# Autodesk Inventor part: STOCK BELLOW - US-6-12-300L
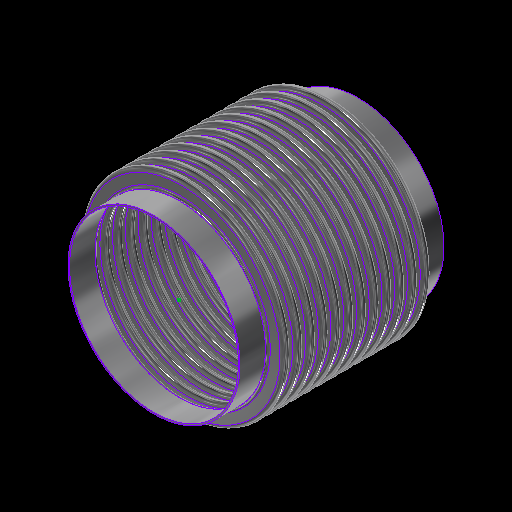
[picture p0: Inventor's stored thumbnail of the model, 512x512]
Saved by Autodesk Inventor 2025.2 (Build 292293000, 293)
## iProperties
Category: 22 GA (0.030 THICK)
RuleStatus: InUse
Created: 2024-01
Part Number: STOCK BELLOW - US-6-12-300L
Project: =STOCK BELLOWS: <Stock Number><SFILL>
Material: ASTM A240-304
Description: =STOCK BELLOWS: <Stock Number>, <SID_> I.D., <SOD_> O.D., <SPLY_> PLY, <Category>, <SNET_CONS> CONS.<PITCH_><STANGENT_> TANGENT<SFILL>
Document SubType Name: Sheet Metal
Designer: GS
Stock Number: U.S-6-12-300L
Surface Area: 6070.08 cm^2
Volume: 458.823 cm^3
Sheet Metal Rule: Default
Appearance: STAINLESS STEEL
Mass: 3696.87 g
Density: 8.05729 g/cm^3
THK: 0.036
ID: 3.500
OD: 4.250
CONS_: 2
PITCH: 0.500
TANGENT: 0.500
BELLOWS_UPSET: 0.000
d79: 1.000
d82: 1.000
d83: 26.000
d84: 24.000
d174: 8
d214: 8
STHK_: 0.030
SID_: 6.625
SOD_: 8.000
SPITCH_: 0.500
STANGENT__: 1.000
SBELLOWS_UPSET_: 0.000
SDIFF_TAN: 1.000
d252: 2
d275: 2
d287: 0.050
d289: 0.500
d290: 0.000
SOD_NECK: 6 3/4
PLY: 1
PSET: 4.178
PBAR: 1.035
COUNTER: 1.500
NET_TUBE: 3.071
CONS: 2
S_CONS: 0
NET_CONS: 2
ID_M: 88.90 mm
OD_M: 107.95 mm
THK_M: 0.91 mm
ID_U: 3.500 in
OD_U: 4.250 in
THK_U: 0.036 in
TANGENT2: 0.500
TAN_TO_TAN: 1.000 in
d80: 2.571
d81: 10
SID: 2.375
SCONS_: 12
SPITCH: 0.250
STANGENT_: 1.000
SBELLOWS_UPSET: 0.000
SNET_CONS: 12
SS_CONS: 0
SCONS: 8
d190: 8
d191: 1
d192: 1
d193: 8
d194: 0
SIZE: 6.00
PRESSURE: 300
d230: 8
STANGENT: 4.000
SPLY_: 2
d233: 8
d234: 0
d263: 2
d265: 1
d268: 2
d269: 0
d286: 2
d288: 1
d291: 2
d292: 0
SREROLL: 0.750
BLETP: 1.000 ul
PRES_Copy: 85
MATTABLE: 20 GA (0.036 THICK)
PART_NUMBER: U.S-6-12-300L
PITCH_: =, <SPITCH_> PITCH,
CFILL: .
SFILL: .
MESH: ,
COMP: 1.26
EXT: 0.63
LAT: 0.34
ANG: 573
ASR: 1872
LSR: 4172
ANSR: 218
PRES: 300
COMPM: 12.6
EXTM: 6.3
LATM: 3.40
ASRM: 327.843
PRESM: 20.684
LSRM: 730.642
ANSRM: 38.178
TEMPMIN: 20
TEMPMAX: 800
TEMPMINM: -7
TEMPMAXM: 427
WEIGHTM: 3.697
WEIGHT: 8.150
Author: GS
Keywords: 20 GA (0.036 THICK)
Comments: =STOCK BELLOW - <STOCK NUMBER>
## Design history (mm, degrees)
sketch "Sketch2"
  geometry: L1 (0, -177.245)-(0, 562.856) reference; L2 (45.364, 0)-(44.45, 0); L3 (48.082, -2.718)-(50.343, -2.718); L4 (48.082, -3.632)-(50.343, -3.632); L5 (50.343, -9.982)-(48.082, -9.982); L6 (50.343, -9.068)-(48.082, -9.068); L7 (45.364, -12.7)-(44.45, -12.7); L8 (48.082, 0)-(48.082, -12.7); L9 (50.343, -6.35)-(53.975, -6.35); L10 (44.45, 0)-(44.45, -12.7); L11 (20.376, 102.841)-(20.376, 101.926); L12 (58.262, 457.127)-(58.262, 349.177); L13 (58.262, 444.427)-(58.262, 336.477); L14 (93.133, -58.817)-(93.133, -71.517); L15 (118.746, -66.401)-(118.746, -66.401); L16 (50.343, -9.068)-(50.343, -9.982); L17 (48.082, -9.068)-(48.082, -9.982); L18 (48.082, -9.525)-(50.343, -9.525); L19 (53.975, 0)-(53.975, -12.7); L20 (-50.343, -9.068)-(-50.343, -9.982); L21 (-50.343, -2.718)-(-48.082, -2.718); L22 (-50.343, -3.632)-(-48.082, -3.632); L23 (-48.082, -9.068)-(-50.343, -9.068); L24 (-50.343, -9.525)-(-48.082, -9.525); L25 (-48.082, -9.982)-(-50.343, -9.982); L26 (-48.082, -9.068)-(-48.082, -9.982); L27 (-44.45, 0.653)-(-44.45, -12.047); L28 (-48.082, -6.35)-(-44.45, -6.35); L29 (-50.343, 0.653)-(-50.343, -12.7); L30 (-53.061, 0)-(-53.975, 0); L31 (-53.975, 0)-(-53.975, -12.7); L32 (-53.061, -12.7)-(-53.975, -12.7); A1 r 2.718 centre (48.082, 0) between (45.364, 0) and (48.082, -2.718); A2 r 3.632 centre (48.082, 0) between (44.45, 0) and (48.082, -3.632); A3 r 3.632 centre (50.343, -6.35) between (50.343, -9.982) and (50.343, -2.718); A4 r 2.718 centre (50.343, -6.35) between (50.343, -9.068) and (50.343, -3.632); A5 r 2.718 centre (48.082, -12.7) between (48.082, -9.982) and (45.364, -12.7); A6 r 3.632 centre (48.082, -12.7) between (48.082, -9.068) and (44.45, -12.7); A7 r 3.175 centre (50.343, -6.35) between (50.343, -9.525) and (53.518, -6.35); A8 r 3.175 centre (48.082, -12.7) between (48.082, -9.525) and (44.907, -12.7); A9 r 2.718 centre (-50.343, -12.7) between (-50.343, -9.982) and (-53.061, -12.7); A10 r 2.718 centre (-48.082, -6.35) between (-48.082, -9.068) and (-48.082, -3.632); A11 r 3.175 centre (-48.082, -6.35) between (-48.082, -9.525) and (-44.907, -6.35); A12 r 3.632 centre (-48.082, -6.35) between (-48.082, -9.982) and (-48.082, -2.718); A13 r 3.175 centre (-50.343, -12.7) between (-50.343, -9.525) and (-53.518, -12.7); A14 r 3.632 centre (-50.343, -12.7) between (-50.343, -9.068) and (-53.975, -12.7); A15 r 2.718 centre (-50.343, 0) between (-53.061, 0) and (-50.343, -2.718); A16 r 3.632 centre (-50.343, 0) between (-53.975, 0) and (-50.343, -3.632); 10 further points
  constraints: 62 end point, 38 point on circle, 20 tangent, 16 centre point, 12 parallel, 9 midpoint, 7 vertical, 6 coincident, 6 concentric, 6 point on line, 4 equal radius, 4 perpendicular, 3 horizontal, 1 collinear, 1 horizontal alignment, 10 other
  dimensions: "THK" = 0.9144 distance of L11.start L11.end; "ID" = 88.9 distance of L11.end point (20.376, 13.026); "OD" = 107.95 distance of L12.start L12.end; "PITCH" = 12.7 distance of L12.start L13.start; "TANGENT" = 12.7 distance of L14.start L14.end; "BELLOWS_UPSET" = 0 distance of L15.start L15.end; "d43" = 88.9 diameter of L10 L1 (= ID); "d44" = 107.95 diameter of L9.end L1 (= OD); "d45" = 0.9144 distance between parallel lines of L5 L6 (computed from THK, PLY); "d46" = 3.6322 radius of A3 (computed from PITCH, THK, PLY); "UPSET_PITCH" = 12.7 distance of L2.end L7.end (derived); "SIDEWALL_ANGLE" = 360 deg dimension on L3 L9 (derived); "CON_GAP" = 5.4356 distance of point (48.082, -9.068) point (48.082, -3.632) (derived); "TAN1" = 4.98728 dimension on A8 (derived); "TAN2" = 4.98728 dimension on A7 (derived); "LEG1" = 2.2606 distance of L18.start L18.end (derived); "d278" = 0.9144 distance between parallel lines of L25 L23 (derived); "d279" = 3.6322 radius of A12 (derived); "d280" = 12.7 distance of L30.end L31.end (derived); "d281" = 360 deg dimension on L21 L28 (derived); "d282" = 5.4356 distance of point (-50.343, -9.068) point (-50.343, -3.632) (derived); "d283" = 4.98728 dimension on A13 (derived); "d284" = 4.98728 dimension on A11 (derived); "d285" = 2.2606 distance of L24.start L24.end (derived); "d293" = 88.9 diameter of L27 L1 (derived); "d294" = 107.95 diameter of L31 L1 (derived)
  node "Sketch Rectangular Pattern1" dims "d31" = 25.4, "ID" = 88.9
  node "Sketch Rectangular Pattern2" dims "d39" = 25.4, "PITCH" = 12.7
revolve "CONS" stored, may be unused: angle "d48" = 90 deg
node "BELLOW MIDPLANE"
pattern_linear "Rectangular Pattern2" dims "d52" = 12.7 (= UPSET_PITCH)
sketch "Sketch5"
  geometry: C1 r 45.364 at (0, 0) reference; C2 r 44.45 at (0, 0) reference
extrude "TANGENT" new body sketch "Sketch5" distance "d53" = 12.7 (= TANGENT); taper "d54" = 0 deg
revolve "SAMETAN" stored, may be unused: angle "d65" = 90 deg
revolve "DIFFTAN" stored, may be unused: angle "d70" = 90 deg
sketch "Sketch9"
  geometry: L1 (53.319, 0)-(-53.319, 0) reference; L2 (0, -17.78)-(0, 17.78) reference; L3 (38.085, 0)-(-38.085, 0); L4 (38.085, -11.906)-(38.085, 11.906); L5 (25.385, -11.906)-(25.385, 11.906); L6 (13.15, 11.906)-(13.15, -11.906); L7 (-25.385, -11.906)-(-25.385, 11.906); L8 (-38.085, -11.906)-(-38.085, 11.906); L9 (37.291, -11.906)-(37.291, 11.906); L10 (38.085, -11.906)-(37.291, -11.906); L11 (38.085, 11.906)-(37.291, 11.906); L12 (13.546, 11.906)-(12.753, 11.906); L13 (12.753, 11.906)-(12.753, -11.906); L14 (12.753, -11.906)-(13.546, -11.906); L15 (13.546, -11.906)-(13.546, 11.906); L16 (-13.546, 11.906)-(-13.546, -11.906); L17 (-13.15, 11.906)-(-13.15, -11.906); L18 (-13.546, -11.906)-(-12.753, -11.906); L19 (-12.753, -11.906)-(-12.753, 11.906); L20 (-12.753, 11.906)-(-13.546, 11.906); L21 (-38.085, -11.906)-(-37.291, -11.906); L22 (-37.291, -11.906)-(-37.291, 11.906); L23 (-37.291, 11.906)-(-38.085, 11.906); L24 (-38.085, 11.906)-(-38.085, -11.906); L25 (38.085, -0.397)-(-38.085, -0.397); L26 (-38.085, -0.397)-(-38.085, 0.397); L27 (-38.085, 0.397)-(38.085, 0.397); L28 (38.085, 0.397)-(38.085, -0.397); L29 (-38.085, 11.906)-(38.085, 11.906); L30 (38.085, 11.906)-(38.085, 12.7); L31 (38.085, 12.7)-(-38.085, 12.7); L32 (-38.085, 12.7)-(-38.085, 11.906); L33 (38.085, -11.906)-(-38.085, -11.906); L34 (-38.085, -11.906)-(-38.085, -12.7); L35 (-38.085, -12.7)-(38.085, -12.7); L36 (38.085, -12.7)-(38.085, -11.906); 30 further points
  constraints: 68 end point, 13 midpoint, 13 parallel, 8 horizontal, 7 perpendicular, 6 equal length, 3 point on line, 2 vertical, 14 other
  dimensions: "d115" = 23.8125 distance of L4.start L4.end (derived); "d116" = 12.7 distance between parallel lines of L4 L5 (derived); "d117" = 12.23516 distance between parallel lines of L5 L6 (derived); "d125" = 38.53427 distance between parallel lines of L7 L6 (derived); "d127" = 12.7 distance between parallel lines of L8 L7 (derived); "d128" = 24.93516 distance between parallel lines of L6 L4 (derived); "d130" = 76.16943 distance between parallel lines of L8 L4 (derived); "RULER_THK" = 0.79375 distance between parallel lines of L4 L9; "d135" = 0.79375 distance of L13.end L14.end (derived); "d138" = 26.29911 distance of L13.end L16.end (derived); "d143" = 0.79375 distance of L22.end L8.end (derived); "d144" = 0.79375 distance between parallel lines of L27 L25 (derived)
extrude "RULER" join sketch "Sketch9" distance "d149" = 0.79375 (derived); taper "d150" = 0 deg
extrude "BARS" join sketch "Sketch9" distance "d151" = 0.79375 (derived); taper "d152" = 0 deg
pattern_linear "Rectangular Pattern4" dims "d155" = 26.29911 (derived)
sketch "Sketch13"
  geometry: L1 (93.149, -52.467)-(93.149, -77.867); L2 (85.662, 0)-(84.138, 0); L3 (85.662, -12.7)-(84.138, -12.7); L4 (97.663, -10.287)-(88.075, -10.287); L5 (97.663, -8.763)-(88.075, -8.763); L6 (97.663, -6.35)-(101.6, -6.35); L7 (88.075, -2.413)-(97.663, -2.413); L8 (88.075, 0)-(88.075, -12.7); L9 (84.138, 0)-(84.138, -12.7); L10 (58.254, -293.231)-(58.254, -496.431); L11 (58.254, -305.931)-(58.254, -509.131); L12 (58.254, -331.331)-(58.254, -534.531); L13 (58.254, -344.031)-(58.254, -547.231); L14 (58.254, -356.731)-(58.254, -559.931); L15 (58.254, -369.431)-(58.254, -572.631); L16 (58.254, -382.131)-(58.254, -585.331); L17 (58.254, -318.631)-(58.254, -521.831); L18 (20.376, 102.688)-(20.376, 101.926); L19 (88.075, -3.937)-(97.663, -3.937); L20 (0, -722.935)-(0, 240.292) reference; L21 (-23.752, 0)-(142.514, 0) reference; A1 r 2.413 centre (88.075, 0) between (85.662, 0) and (88.075, -2.413); A2 r 2.413 centre (88.075, -12.7) between (88.075, -10.287) and (85.662, -12.7); A3 r 3.937 centre (88.075, -12.7) between (88.075, -8.763) and (84.138, -12.7); A4 r 2.413 centre (97.663, -6.35) between (97.663, -8.763) and (97.663, -3.937); A5 r 3.937 centre (97.663, -6.35) between (97.663, -10.287) and (97.663, -2.413); A6 r 3.937 centre (88.075, 0) between (84.138, 0) and (88.075, -3.937); 6 further points; 1 other entity
  constraints: 38 end point, 15 point on circle, 9 tangent, 6 centre point, 6 parallel, 5 vertical alignment, 4 point on line, 4 vertical, 3 coincident, 3 concentric, 2 collinear, 2 equal radius, 1 horizontal, 1 perpendicular, 23 other
  dimensions: "SBELLOWS_UPSET_" = 0 distance of point (118.762, -66.401) point (118.762, -66.401); "STOTAL_THK_BELLOW__" = 1.524 distance between parallel lines of L4 L5 (derived); "d224" = 3.937 radius of A5 (derived); "d225" = 12.7 distance of L2.end L3.end (derived); "SSIDEWALL_ANGLE_" = 0 deg angle of L7 L6 (derived); "SSCON_GAP_" = 4.826 distance of point (88.075, -8.763) point (88.075, -3.937) (derived); "d235" = 168.275 diameter of L9 L20 (derived); "d236" = 203.2 diameter of L6.end L20 (derived)
  node "Sketch Rectangular Pattern4" dims "d228" = 25.4
  node "Sketch Rectangular Pattern5" dims "d229" = 25.4
revolve "SBELLOW" stored, may be unused: angle "d197" = 90 deg
pattern_linear "Rectangular Pattern5" dims "d204" = 12.7 (derived)
revolve "STANGENT" stored, may be unused: angle "d240" = 90 deg
revolve "SSAMETAN" stored, may be unused: angle "d241" = 90 deg
revolve "SDIFFTAN" stored, may be unused: angle "d246" = 90 deg
revolve "INVCON" stored, may be unused: angle "d295" = 90 deg
pattern_linear "Rectangular Pattern6" dims "d298" = 12.7 (derived)
revolve "INVTANGENT" stored, may be unused: angle "d302" = 90 deg
revolve "INVSAMETAN" stored, may be unused: angle "d307" = 90 deg
revolve "INVDIFFTAN" stored, may be unused: angle "d312" = 90 deg
sketch "ID BELLOW MOUNT CALC"
  geometry: L1 (44.45, 0)-(38.1, 0); L2 (38.1, 0)-(38.1, 12.7); L3 (38.1, 12.7)-(44.45, 12.7); L4 (44.45, 12.7)-(44.45, 0); L5 (36.513, 12.7)-(35.598, 12.7); L6 (35.598, 12.7)-(35.598, 0); L7 (35.598, 0)-(36.513, 0); L8 (36.513, 0)-(36.513, 12.7); L9 (0, -2.54)-(0, 15.24) reference; L10 (-8.89, 0)-(53.34, 0) reference; 1 further point
  constraints: 16 end point, 5 parallel, 2 collinear, 2 horizontal, 2 perpendicular
  dimensions: "d314" = 12.7 distance of L5.end L6.end (derived); "d315" = 0.9144 distance of L5.start L5.end (derived); "IG" = 1.5875 distance between parallel lines of L2 L8; "PIPE_OD" = 88.9 diameter of L4 L9; "PIPE_WALL" = 6.35 distance of L2.end L3.end; "ID_MT_BELLOW" = 71.1962 diameter of L6 L9 (derived)
revolve "CFILL" stored, may be unused: angle "d320" = 90 deg
pattern_linear "Rectangular Pattern7" dims "d323" = 12.7 (derived)
revolve "SFILL" stored, may be unused: angle "d324" = 90 deg
pattern_linear "Rectangular Pattern8" dims "d327" = 12.7 (derived)
node "STOCK BELLOW MIDPLANE"
node "BELLOW"
sketch "Sketch6"
  geometry: L1 (-12.7, 45.364)-(0, 45.364); L2 (0, 45.364)-(0, 44.45); L3 (0, 44.45)-(-12.7, 44.45); L4 (-12.7, 44.45)-(-12.7, 45.364); L5 (10.16, 0)-(-60.96, 0) reference; L6 (-38.1, -89.422)-(-38.1, 153.44) reference; 1 further point
  constraints: 8 end point, 2 parallel, 1 horizontal, 1 perpendicular
  dimensions: "d61" = 12.7 distance of L2.end L3.end (derived); "d62" = 0.9144 distance of L1.end L2.end (derived); "d63" = 88.9 diameter of L3 L5 (derived); "d64" = 25.4 distance between parallel lines of L4 L6 (derived)
sketch "Sketch12"
  geometry: 1 further point
sketch "Sketch14"
  geometry: L1 (-25.4, 85.662)-(0, 85.662); L2 (0, 85.662)-(0, 84.138); L3 (0, 84.138)-(-25.4, 84.138); L4 (-25.4, 84.138)-(-25.4, 85.662); L5 (5.08, 0)-(-30.48, 0) reference; L6 (0, -17.132)-(0, 102.794) reference; 1 further point
  constraints: 8 end point, 2 parallel, 1 collinear, 1 horizontal, 1 perpendicular
  dimensions: "d237" = 1.524 distance of L3.end L1.start (derived); "d238" = 168.275 diameter of L3 L5 (derived); "d239" = 25.4 distance of L1.start L1.end (derived); "SOD_NECK" = 171.323 diameter of L1 L5 (derived)
sketch "Sketch15"
  geometry: L1 (-17.132, 0)-(102.794, 0) reference; L2 (84.138, -152.4)-(85.662, -152.4); L3 (85.662, -152.4)-(85.662, -177.8); L4 (85.662, -177.8)-(84.138, -177.8); L5 (84.138, -177.8)-(84.138, -152.4); L6 (0, -215.9)-(0, 50.8) reference; 1 further point
  constraints: 8 end point, 2 parallel, 1 horizontal, 1 perpendicular
  dimensions: "d205" = 25.4 distance of L4.end L2.start (derived); "d206" = 1.524 distance of L3.end L4.end (derived); "d207" = 168.275 diameter of L5 L6 (derived); "d208" = 152.4 distance between parallel lines of L1 L2 (derived)
node "TANGENT_"
node "SAME_TAN"
sketch "Sketch8"
  geometry: L1 (45.364, -25.4)-(44.45, -25.4); L2 (44.45, -25.4)-(44.45, -38.1); L3 (44.45, -38.1)-(45.364, -38.1); L4 (45.364, -38.1)-(45.364, -25.4); L5 (0, -48.26)-(0, 22.86) reference; L6 (-89.422, 0)-(153.44, 0) reference; 1 further point
  constraints: 8 end point, 2 parallel, 1 horizontal, 1 perpendicular
  dimensions: "d66" = 88.9 diameter of L2 L5 (derived); "TOTAL_THK_BELLOW" = 0.9144 distance of L2.end L3.end (derived); "d68" = 25.4 distance between parallel lines of L1 L6 (derived); "d69" = 12.7 distance of L1.end L2.end (derived)
node "DIFF_TAN"
node "Sketch Rectangular Pattern3" dims "d138" = 26.29911 (derived), "d141" = 25.4
node "SBELLOW_"
node "STANGENT_"
node "SSAME_TAN"
sketch "Sketch16"
  geometry: L1 (85.661, -152.4)-(84.138, -152.4); L2 (84.138, -152.4)-(84.138, -177.8); L3 (84.138, -177.8)-(85.662, -177.8); L4 (85.662, -177.8)-(85.661, -152.4); L5 (0, -215.9)-(0, 50.8) reference; L6 (-17.132, 0)-(102.794, 0) reference; 1 further point
  constraints: 8 end point, 2 parallel, 1 horizontal, 1 perpendicular
  dimensions: "SDIFF_TAN" = 25.4 distance of L3.end L1.start; "d243" = 1.524 distance of L2.end L3.end (derived); "d244" = 152.4 distance between parallel lines of L1 L6 (derived); "d245" = 168.275 diameter of L2 L5 (derived)
node "SDIFF_TAN"
body "Solid15"
sketch "Sketch17"
  geometry: L1 (53.975, 12.7)-(53.061, 12.7); L2 (53.061, 12.7)-(53.061, 0); L3 (53.061, 0)-(53.975, 0); L4 (53.975, 0)-(53.975, 12.7); L5 (0, -2.54)-(0, 15.24) reference; L6 (-10.795, 0)-(64.77, 0) reference; 2 further points
  constraints: 8 end point, 2 parallel, 1 horizontal, 1 midpoint, 1 perpendicular, 1 point on line
  dimensions: "INVTANGENT" = 12.7 distance of L3.end L1.start (derived); "d300" = 0.9144 distance of L1.start L1.end (derived); "d301" = 107.95 diameter of L4 L5 (derived)
body "Solid16"
sketch "Sketch18"
  geometry: L1 (53.975, -25.4)-(53.061, -25.4); L2 (53.061, -25.4)-(53.061, -38.1); L3 (53.061, -38.1)-(53.975, -38.1); L4 (53.975, -38.1)-(53.975, -25.4); L5 (-10.795, 0)-(64.77, 0) reference; L6 (0, -48.26)-(0, 22.86) reference; 1 further point
  constraints: 8 end point, 2 parallel, 1 horizontal, 1 perpendicular
  dimensions: "d303" = 25.4 distance between parallel lines of L1 L5 (derived); "d304" = 12.7 distance of L3.end L1.start (derived); "d305" = 0.9144 distance of L2.end L3.end (derived); "d306" = 107.95 diameter of L4 L6 (derived)
body "Solid17"
sketch "Sketch19"
  geometry: L1 (53.975, -25.4)-(53.061, -25.4); L2 (53.061, -25.4)-(53.061, -38.1); L3 (53.061, -38.1)-(53.975, -38.1); L4 (53.975, -38.1)-(53.975, -25.4); L5 (0, -48.26)-(0, 22.86) reference; L6 (-10.795, 0)-(64.77, 0) reference; 1 further point
  constraints: 8 end point, 2 parallel, 1 horizontal, 1 perpendicular
  dimensions: "d308" = 12.7 distance of L1.end L2.end (derived); "d309" = 107.95 diameter of L4 L5 (derived); "d310" = 0.9144 distance of L2.end L3.end (derived); "d311" = 25.4 distance between parallel lines of L1 L6 (derived)
body "Solid18"
body "Solid19"
body "Solid20"
other parameters: "BMPL" = -76.2, "PSET" = 106.1212 (computed from OD, THK, PLY) [user parameter], "PBAR" = 26.29911 (= 0.570796 x PITCH + OD - ID) [user parameter; used in 1 equation term], "COUNTER" = 15 [user parameter], "NET_TUBE" = 77.99823 (computed from CONS_, PBAR, TANGENT) [user parameter], "S_CONS" = 0 [user parameter; used in 1 equation term], "ID_M" = 88.9 (= ID) [user parameter], "OD_M" = 107.95 (= OD) [user parameter], "THK_M" = 0.9144 (= THK) [user parameter], "ID_U" = 88.9 (= ID) [user parameter], "OD_U" = 107.95 (= OD) [user parameter], "THK_U" = 0.9144 (= THK) [user parameter], "D_UNITS" = 0 [user parameter], "TANGENT2" = 12.7 [user parameter], "TAN_TO_TAN" = 25.4 [user parameter], "OD_NECK" = 90.7288 [user parameter], "d79" = 25.4, "d80" = 65.29823 [user parameter], "d82" = 25.4, "d83" = 660.4, "d84" = 609.6, "sa_0" = 4, "FRAME_THK" = 0.79375 [user parameter], "CON_FLAT" = 12.23516 [user parameter], "SID" = 60.325 [user parameter], "SPITCH" = 6.35 [user parameter], "STANGENT_" = 25.4 [user parameter], "SBELLOWS_UPSET" = 0 [user parameter], "SS_CONS" = 0 [user parameter], "STAN_TO_TAN_" = 152.4 [user parameter], "d100" = 1.524 [user parameter], "d191" = 25.4 [user parameter], "d194" = 0 [user parameter], "STANGENT" = 101.6 [user parameter], "d234" = 0 [user parameter], "SUPSET_PITCH_" = 12.7 [user parameter], "d269" = 0 [user parameter], "d287" = 1.27, "d289" = 12.7, "d290" = 0, "d292" = 0 [user parameter], "Thickness" = 3.048 (derived), "KFactor" = 4.4, "BendRadius" = 3.048 (derived), "BendReliefWidth" = 3.048 (derived), "BendReliefDepth" = 1.524 (derived), "CornerReliefSize" = 12.192 (derived), "SeamGap" = 0.00508, "MinimumRemnant" = 6.096 (derived), "TransitionRadius" = 3.048 (derived), "JacobiRadiusSize" = 3.048 (derived), "GapSize" = 3.048 (derived), "SREROLL" = 19.05 [user parameter], "CUR_STK_PITCH" = 12.7 [user parameter], "d328" = -76.2 (derived), "ASR" = 18720 [user parameter], "LSR" = 41720 [user parameter], "BLETP" = 1 [user parameter], "ASRM" = 3278.4336 [user parameter], "PRESM" = 206.83949 [user parameter], "LSRM" = 7306.4236 [user parameter], "ANSRM" = 381.7834 [user parameter], "TEMPMIN" = 2664.83333 [user parameter], "TEMPMAX" = 6998.16667 [user parameter], "TEMPMINM" = 2664.83333 [user parameter], "TEMPMAXM" = 6998.16667 [user parameter], "WEIGHT" = 36.96871 [user parameter], "WEIGHTM" = 0.03697 [user parameter]
